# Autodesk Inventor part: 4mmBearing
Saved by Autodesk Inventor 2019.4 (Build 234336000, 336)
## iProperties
Created: 2020-02
Part Number: 4mmBearing
Material: Generic
Document SubType Name: Modeling
Designer: Administrator
Density: 1 g/cm^3
Appearance: Default
Title: 4mmBearing
Author: Administrator
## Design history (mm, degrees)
feature "Body1"
body "Solid1"
